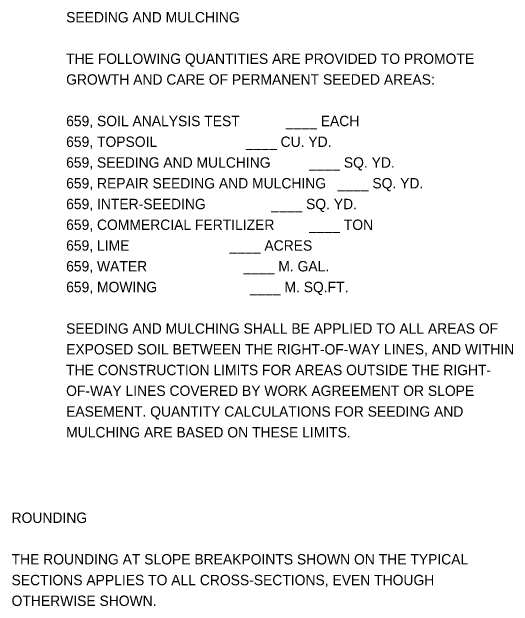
# Model space of a CAD drawing. Extents: x -7.5 to 43.2, y 0 to 22.
# Drawn here: x 36.41 to 43.17, y 9.03 to 17.05 of the extents above; entities that cross this region are included whole.
import ezdxf

# ---------------------------------------------------------------- set-up
doc = ezdxf.new("R2010")
doc.units = 0
doc.layers.add('SH_Text', color=7, linetype='Continuous')

msp = doc.modelspace()

# ---------------------------------------------------------------- texts
at = {"layer": 'SH_Text'}
for s, p in [('SEEDING AND MULCHING', (37.1431, 16.9085)), ('THE FOLLOWING QUANTITIES ARE PROVIDED TO PROMOTE', (37.1431, 16.3485)), ('GROWTH AND CARE OF PERMANENT SEEDED AREAS:', (37.1431, 16.0685)), ('659, SOIL ANALYSIS TEST            ____ EACH', (37.1431, 15.5085)), ('659, TOPSOIL                       ____ CU. YD.', (37.1431, 15.2285)), ('659, SEEDING AND MULCHING          ____ SQ. YD.', (37.1431, 14.9485)), ('659, REPAIR SEEDING AND MULCHING   ____ SQ. YD.', (37.1431, 14.6685)), ('659, INTER-SEEDING                 ____ SQ. YD.', (37.1431, 14.3885)), ('659, COMMERCIAL FERTILIZER         ____ TON', (37.1431, 14.1085)), ('659, LIME                          ____ ACRES', (37.1431, 13.8285)), ('659, WATER                         ____ M. GAL.', (37.1431, 13.5485)), ('659, MOWING                        ____ M. SQ.FT.', (37.1431, 13.2685)), ('SEEDING AND MULCHING SHALL BE APPLIED TO ALL AREAS OF', (37.1431, 12.7085)), ('EXPOSED SOIL BETWEEN THE RIGHT-OF-WAY LINES, AND WITHIN', (37.1431, 12.4285)), ('THE CONSTRUCTION LIMITS FOR AREAS OUTSIDE THE RIGHT-', (37.1431, 12.1485)), ('OF-WAY LINES COVERED BY WORK AGREEMENT OR SLOPE', (37.1431, 11.8685)), ('EASEMENT. QUANTITY CALCULATIONS FOR SEEDING AND', (37.1431, 11.5885)), ('MULCHING ARE BASED ON THESE LIMITS.', (37.1431, 11.3085)), ('ROUNDING', (36.4074, 10.1547)), ('THE ROUNDING AT SLOPE BREAKPOINTS SHOWN ON THE TYPICAL', (36.4074, 9.5947)), ('SECTIONS APPLIES TO ALL CROSS-SECTIONS, EVEN THOUGH', (36.4074, 9.3147)), ('OTHERWISE SHOWN.', (36.4074, 9.0347))]:
    msp.add_text(s, height=0.14, dxfattribs=at).set_placement(p)

doc.saveas('drawing.dxf')
